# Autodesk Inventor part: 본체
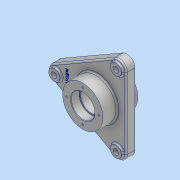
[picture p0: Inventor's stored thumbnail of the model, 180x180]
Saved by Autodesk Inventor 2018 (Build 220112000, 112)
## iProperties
Created: 2023-04
Part Number: 본체
Material: 알루미늄 6061
Document SubType Name: Modeling
Designer: home
Density: 2.7 g/cm^3
Appearance: 알루미늄 - 평지
Mass: 1219.03 g
Surface Area: 640.875 cm^2
Volume: 451.494 cm^3
Author: home
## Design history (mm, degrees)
sketch "스케치1" dims "d0" = 57
  geometry: L1 (-33, 84.87)-(90, 13.856); L2 (90, -13.856)-(-33, -84.87); L3 (-57, -71.014)-(-57, 71.014); A1 r 16 centre (82, 0) between (90, -13.856) and (90, 13.856); A2 r 16 centre (-41, 71.014) between (-33, 84.87) and (-57, 71.014); A3 r 16 centre (-41, -71.014) between (-57, -71.014) and (-33, -84.87); 7 further points
  constraints: 6 end point, 6 point on circle, 6 point on line, 6 tangent, 3 centre point, 2 coincident, 2 equal radius, 1 horizontal alignment, 1 midpoint, 9 other
  dimensions: "d1" = 16 radius of A1
extrude "돌출1" new body sketch "스케치1" distance "d2" = 18; taper "d3" = 0 deg
sketch "스케치2"
  geometry: C1 r 45 at (0, 0); 1 further point
  constraints: 1 centre point, 1 coincident
  dimensions: "d5" = 90 diameter of C1
extrude "돌출2" join sketch "스케치2" distance "d6" = 5; taper "d7" = 0 deg
node "작업 평면1"
sketch "스케치3"
  geometry: C1 r 40 at (0, 0); 1 further point
  constraints: 1 centre point, 1 coincident
  dimensions: "d9" = 80 diameter of C1
extrude "돌출3" join sketch "스케치3" distance "d10" = 70; taper "d11" = 0 deg
sketch "스케치4"
  geometry: L1 (-90, -13.856)-(33, -84.87) reference; L2 (57, -71.014)-(57, 71.014) reference; L3 (33, 84.87)-(-90, 13.856) reference; C1 r 40 at (0, 0) reference; C2 r 40 at (0, 0) reference; C3 r 11 at (-82, 0); C4 r 11 at (41, -71.014); C5 r 11 at (41, 71.014); A1 r 16 centre (41, -71.014) between (33, -84.87) and (57, -71.014) reference; A2 r 16 centre (41, 71.014) between (57, 71.014) and (33, 84.87) reference; A3 r 16 centre (-82, 0) between (-90, 13.856) and (-90, -13.856) reference; 1 further point
  constraints: 3 centre point, 2 coincident
  dimensions: "d13" = 22 diameter of C3; "d14" = 22 diameter of C4; "d15" = 22 diameter of C5
extrude "돌출4" join sketch "스케치4" distance "d16" = 4; taper "d17" = 0 deg
hole "구멍1" diameter "d20" = 11; stored, may be unused: countersink angle "d24" = 90 deg, drill point angle "d26" = 118 deg; dims "d18" = 10, "d19" = 10, "d21" = 6, "d22" = 4, "d23" = 2, "d25" = 8
hole "구멍2" diameter "d29" = 11; stored, may be unused: countersink angle "d33" = 90 deg, drill point angle "d35" = 118 deg; dims "d27" = 10, "d28" = 10, "d30" = 6, "d31" = 4, "d32" = 2, "d34" = 8
hole "구멍3" diameter "d38" = 11; stored, may be unused: countersink angle "d42" = 90 deg, drill point angle "d44" = 118 deg; dims "d36" = 10, "d37" = 10, "d39" = 6, "d40" = 4, "d41" = 2, "d43" = 8
hole "구멍4" diameter "d47" = 42; stored, may be unused: countersink angle "d51" = 90 deg, drill point angle "d53" = 118 deg; dims "d45" = 10, "d46" = 10, "d48" = 6, "d49" = 47, "d50" = 17, "d52" = 70
hole "구멍5" diameter "d56" = 42; stored, may be unused: countersink angle "d60" = 90 deg, drill point angle "d62" = 118 deg; dims "d54" = 10, "d55" = 10, "d57" = 6, "d58" = 47, "d59" = 17, "d61" = 70
sketch "스케치5"
  geometry: A1 r 32 centre (0, 0) between (-32, 0) and (0, -32); 3 further points
  constraints: 4 point on circle, 1 centre point, 1 coincident
  dimensions: "d63" = 64 diameter of A1
hole "구멍6" sketch "스케치5" at (-32, 0), (0, -32), (32, 0), (0, 32) diameter "d64" = 3.242; stored, may be unused: countersink angle "d68" = 90 deg, drill point angle "d70" = 118 deg; dims "d65" = 8, "d66" = 47, "d67" = 17, "d69" = 10
sketch "스케치6"
  geometry: C1 r 1.621 at (-32, 0) reference; C2 r 1.621 at (32, 0) reference; A1 r 32 centre (0, 0) between (0, -32) and (0, 32); 3 further points
  constraints: 3 coincident, 2 point on circle, 1 centre point
  dimensions: "d71" = 64 diameter of A1
hole "구멍7" sketch "스케치6" at (-32, 0), (0, -32), (32, 0), (0, 32) diameter "d72" = 3.242; stored, may be unused: countersink angle "d76" = 90 deg, drill point angle "d78" = 118 deg; dims "d73" = 8, "d74" = 47, "d75" = 17, "d77" = 10
fillet "모깎기1" dims "d79" = 3
fillet "모깎기2" dims "d80" = 3
fillet "모깎기3" dims "d81" = 3
fillet "모깎기4" dims "d82" = 0.6
chamfer "모따기1" distance "d83" = 1; stored, may be unused: second distance "d84" = 2, angle "d85" = 45 deg
fillet "모깎기5" dims "d86" = 3
sketch "스케치7"
  geometry: 2 further points
  constraints: 1 horizontal alignment, 1 other
  dimensions: "d87" = 60 distance of point (-60, 0) point (0, 0)
feature "엠보싱1" sketch "스케치7" dims "d0" = 57, "d1" = 16, "d88" = 0.5, "d89" = 0
node "솔리드1"
node "투영된 루프1"
node "투영된 루프2"
other parameters: "d8" = 18
